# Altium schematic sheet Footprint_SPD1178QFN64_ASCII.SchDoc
size A4; 项目编号: SPSZ2023-052501A; 项目名称: 三相PFC-2.2KW压机+700W风机
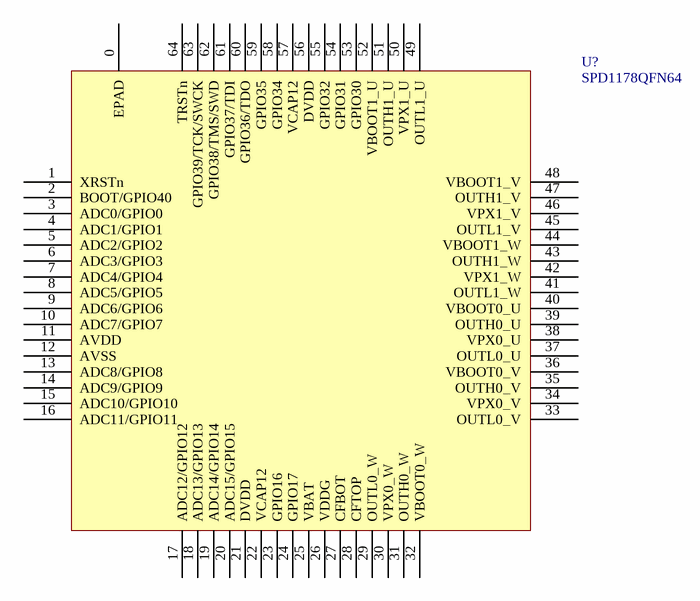
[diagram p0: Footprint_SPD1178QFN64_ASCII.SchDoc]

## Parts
U?  SPD1178QFN64

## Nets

Not connected (* = marked no-connect by the designer): U? 0(EPAD) 1(XRSTn) 2(BOOT/GPIO40) 3(ADC0/GPIO0) 4(ADC1/GPIO1) 5(ADC2/GPIO2) 6(ADC3/GPIO3) 7(ADC4/GPIO4) 8(ADC5/GPIO5) 9(ADC6/GPIO6) 10(ADC7/GPIO7) 11(AVDD) 12(AVSS) 13(ADC8/GPIO8) 14(ADC9/GPIO9) 15(ADC10/GPIO10) 16(ADC11/GPIO11) 17(ADC12/GPIO12) 18(ADC13/GPIO13) 19(ADC14/GPIO14) 20(ADC15/GPIO15) 21(DVDD) 22(VCAP12) 23(GPIO16) 24(GPIO17) 25(VBAT) 26(VDDG) 27(CFBOT) 28(CFTOP) 29(OUTL0_W) 30(VPX0_W) 31(OUTH0_W) 32(VBOOT0_W) 33(OUTL0_V) 34(VPX0_V) 35(OUTH0_V) 36(VBOOT0_V) 37(OUTL0_U) 38(VPX0_U) 39(OUTH0_U) 40(VBOOT0_U) 41(OUTL1_W) 42(VPX1_W) 43(OUTH1_W) 44(VBOOT1_W) 45(OUTL1_V) 46(VPX1_V) 47(OUTH1_V) 48(VBOOT1_V) 49(OUTL1_U) 50(VPX1_U) 51(OUTH1_U) 52(VBOOT1_U) 53(GPIO30) 54(GPIO31) 55(GPIO32) 56(DVDD) 57(VCAP12) 58(GPIO34) 59(GPIO35) 60(GPIO36/TDO) 61(GPIO37/TDI) 62(GPIO38/TMS/SWD) 63(GPIO39/TCK/SWCK) 64(TRSTn)

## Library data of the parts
U? = U_SPD1178QFN64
